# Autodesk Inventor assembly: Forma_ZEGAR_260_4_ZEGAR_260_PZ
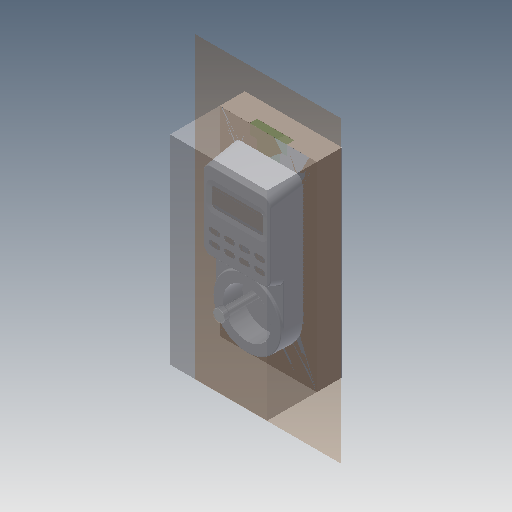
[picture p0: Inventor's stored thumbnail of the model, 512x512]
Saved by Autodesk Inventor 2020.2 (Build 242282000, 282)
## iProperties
Created: 2015-01
Part Number: Forma_ZEGAR_260_4_ZEGAR_260_PZ
Document SubType Name: Assembly
Designer: F.Stasiak
Catalog Web Link: www.expertbooks.pl
Manager: www.cadconsulting.pl
Company: Fabian Stasiak CAD Consulting
Author: F.Stasiak
Subject: Zbiór ćwiczeń. Autodesk Inventor 2020. Kurs Professional
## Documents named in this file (9)
- C:\2020_Kurs_Professional\R6 Formy\Komponenty\Forma_ZEGAR_260_4_ZEGAR_260_PZ.iam
- C:\2020_Kurs_Professional\R6 Formy\Komponenty\Forma_ZEGAR_260_4_ZEGAR_260_MP.ipt
- C:\2020_Kurs_Professional\R6 Formy\Komponenty\Forma_ZEGAR_260_4_ZEGAR_260_WP.ipt
- C:\2020_Kurs_Professional\R6 Formy\Komponenty\Forma_ZEGAR_260_4_ZEGAR_260_CR_Base.ipt
- C:\2020_Kurs_Professional\R6 Formy\Komponenty\Forma_ZEGAR_260_4_ZEGAR_260_CV_Base.ipt
- C:\2020_Kurs_Professional\R6 Formy\Komponenty\Rdzenie formujące\PUNCH_CDH\Forma_ZEGAR_260_4_ZEGAR_260_Rdzeń formujący2_Base.ipt
- C:\2020_Kurs_Professional\R6 Formy\Komponenty\Rdzenie formujące\PUNCH_CDH\Forma_ZEGAR_260_4_ZEGAR_260_Rdzeń formujący2_1.ipt
- C:\2020_Kurs_Professional\R6 Formy\Komponenty\Forma_ZEGAR_260_4_ZEGAR_260_IN1_Base.ipt
- C:\2020_Kurs_Professional\R6 Formy\Komponenty\Forma_ZEGAR_260_4_ZEGAR_260_IN1_1_1.ipt
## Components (8 placed, 8 different names)
1. Forma_ZEGAR_260_4_ZEGAR_260_MP:1 — Równoległy:1, Równoległy:2, Równoległy:3, Równoległy:4, Równoległy:5, Równoległy:6
2. Forma_ZEGAR_260_4_ZEGAR_260_WP:1 — Równoległy:4, Równoległy:5, Równoległy:6
3. Forma_ZEGAR_260_4_ZEGAR_260_CR_Base:1 — Równoległy:7, Równoległy:8, Równoległy:9
4. Forma_ZEGAR_260_4_ZEGAR_260_CV_Base:1 — Równoległy:10, Równoległy:11, Równoległy:12
5. Forma_ZEGAR_260_4_ZEGAR_260_Rdzeń formujący2_Base:1 — Kąt:1, Równoległy:20, Równoległy:21, Równoległy:22, Równoległy:23
6. Forma_ZEGAR_260_4_ZEGAR_260_Rdzeń formujący2_1:1 — Równoległy:20, Równoległy:21, Równoległy:22
7. Forma_ZEGAR_260_4_ZEGAR_260_IN1_Base:1 — Równoległy:24, Równoległy:25, Równoległy:26, Równoległy:27, Równoległy:28, Równoległy:29
8. Forma_ZEGAR_260_4_ZEGAR_260_IN1_1_1:1 — Równoległy:27, Równoległy:28, Równoległy:29
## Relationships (23: Flush 22, Angle 1)
- Równoległy:1 [Flush]: Forma_ZEGAR_260_4_ZEGAR_260_MP:1
- Równoległy:2 [Flush]: Forma_ZEGAR_260_4_ZEGAR_260_MP:1
- Równoległy:3 [Flush]: Forma_ZEGAR_260_4_ZEGAR_260_MP:1
- Równoległy:4 [Flush]: Forma_ZEGAR_260_4_ZEGAR_260_MP:1 ↔ Forma_ZEGAR_260_4_ZEGAR_260_WP:1
- Równoległy:5 [Flush]: Forma_ZEGAR_260_4_ZEGAR_260_MP:1 ↔ Forma_ZEGAR_260_4_ZEGAR_260_WP:1
- Równoległy:6 [Flush]: Forma_ZEGAR_260_4_ZEGAR_260_MP:1 ↔ Forma_ZEGAR_260_4_ZEGAR_260_WP:1
- Równoległy:7 [Flush]: Forma_ZEGAR_260_4_ZEGAR_260_CR_Base:1
- Równoległy:8 [Flush]: Forma_ZEGAR_260_4_ZEGAR_260_CR_Base:1
- Równoległy:9 [Flush]: Forma_ZEGAR_260_4_ZEGAR_260_CR_Base:1
- Równoległy:10 [Flush]: Forma_ZEGAR_260_4_ZEGAR_260_CV_Base:1
- Równoległy:11 [Flush]: Forma_ZEGAR_260_4_ZEGAR_260_CV_Base:1
- Równoległy:12 [Flush]: Forma_ZEGAR_260_4_ZEGAR_260_CV_Base:1
- Kąt:1 [Angle]: Forma_ZEGAR_260_4_ZEGAR_260_Rdzeń formujący2_Base:1
- Równoległy:20 [Flush]: Forma_ZEGAR_260_4_ZEGAR_260_Rdzeń formujący2_Base:1 ↔ Forma_ZEGAR_260_4_ZEGAR_260_Rdzeń formujący2_1:1
- Równoległy:21 [Flush]: Forma_ZEGAR_260_4_ZEGAR_260_Rdzeń formujący2_Base:1 ↔ Forma_ZEGAR_260_4_ZEGAR_260_Rdzeń formujący2_1:1
- Równoległy:22 [Flush]: Forma_ZEGAR_260_4_ZEGAR_260_Rdzeń formujący2_Base:1 ↔ Forma_ZEGAR_260_4_ZEGAR_260_Rdzeń formujący2_1:1
- Równoległy:23 [Flush]: Forma_ZEGAR_260_4_ZEGAR_260_Rdzeń formujący2_Base:1
- Równoległy:24 [Flush]: Forma_ZEGAR_260_4_ZEGAR_260_IN1_Base:1
- Równoległy:25 [Flush]: Forma_ZEGAR_260_4_ZEGAR_260_IN1_Base:1
- Równoległy:26 [Flush]: Forma_ZEGAR_260_4_ZEGAR_260_IN1_Base:1
- Równoległy:27 [Flush]: Forma_ZEGAR_260_4_ZEGAR_260_IN1_Base:1 ↔ Forma_ZEGAR_260_4_ZEGAR_260_IN1_1_1:1
- Równoległy:28 [Flush]: Forma_ZEGAR_260_4_ZEGAR_260_IN1_Base:1 ↔ Forma_ZEGAR_260_4_ZEGAR_260_IN1_1_1:1
- Równoległy:29 [Flush]: Forma_ZEGAR_260_4_ZEGAR_260_IN1_Base:1 ↔ Forma_ZEGAR_260_4_ZEGAR_260_IN1_1_1:1
